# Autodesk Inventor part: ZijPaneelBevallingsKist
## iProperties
Created: 2010-03
Part Number: ZijPaneelBevallingsKist
Document SubType Name: Modeling
Designer: Ferry
Density: 1 g/cm^3
Author: Ferry
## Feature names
1. Extrusion1
